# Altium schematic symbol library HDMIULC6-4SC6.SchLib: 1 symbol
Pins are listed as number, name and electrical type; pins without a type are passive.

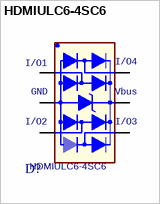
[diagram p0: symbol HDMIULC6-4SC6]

## HDMIULC6-4SC6
designator D?
footprint ST_SOT23-6L
pins: 1 I/O1, 2 GND, 3 I/O2, 4 I/O3, 5 Vbus, 6 I/O4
